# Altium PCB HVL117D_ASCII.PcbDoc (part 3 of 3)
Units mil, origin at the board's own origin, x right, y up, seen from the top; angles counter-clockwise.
Board outline 2004.03 x 2004.03 mil, 6 copper layers (Top Layer, InternalPlane1, MidLayer1, InternalPlane2, MidLayer2, Bottom Layer), stack 60.56 mil thick; 218 components, 157 nets, 658 pads, 273 vias.
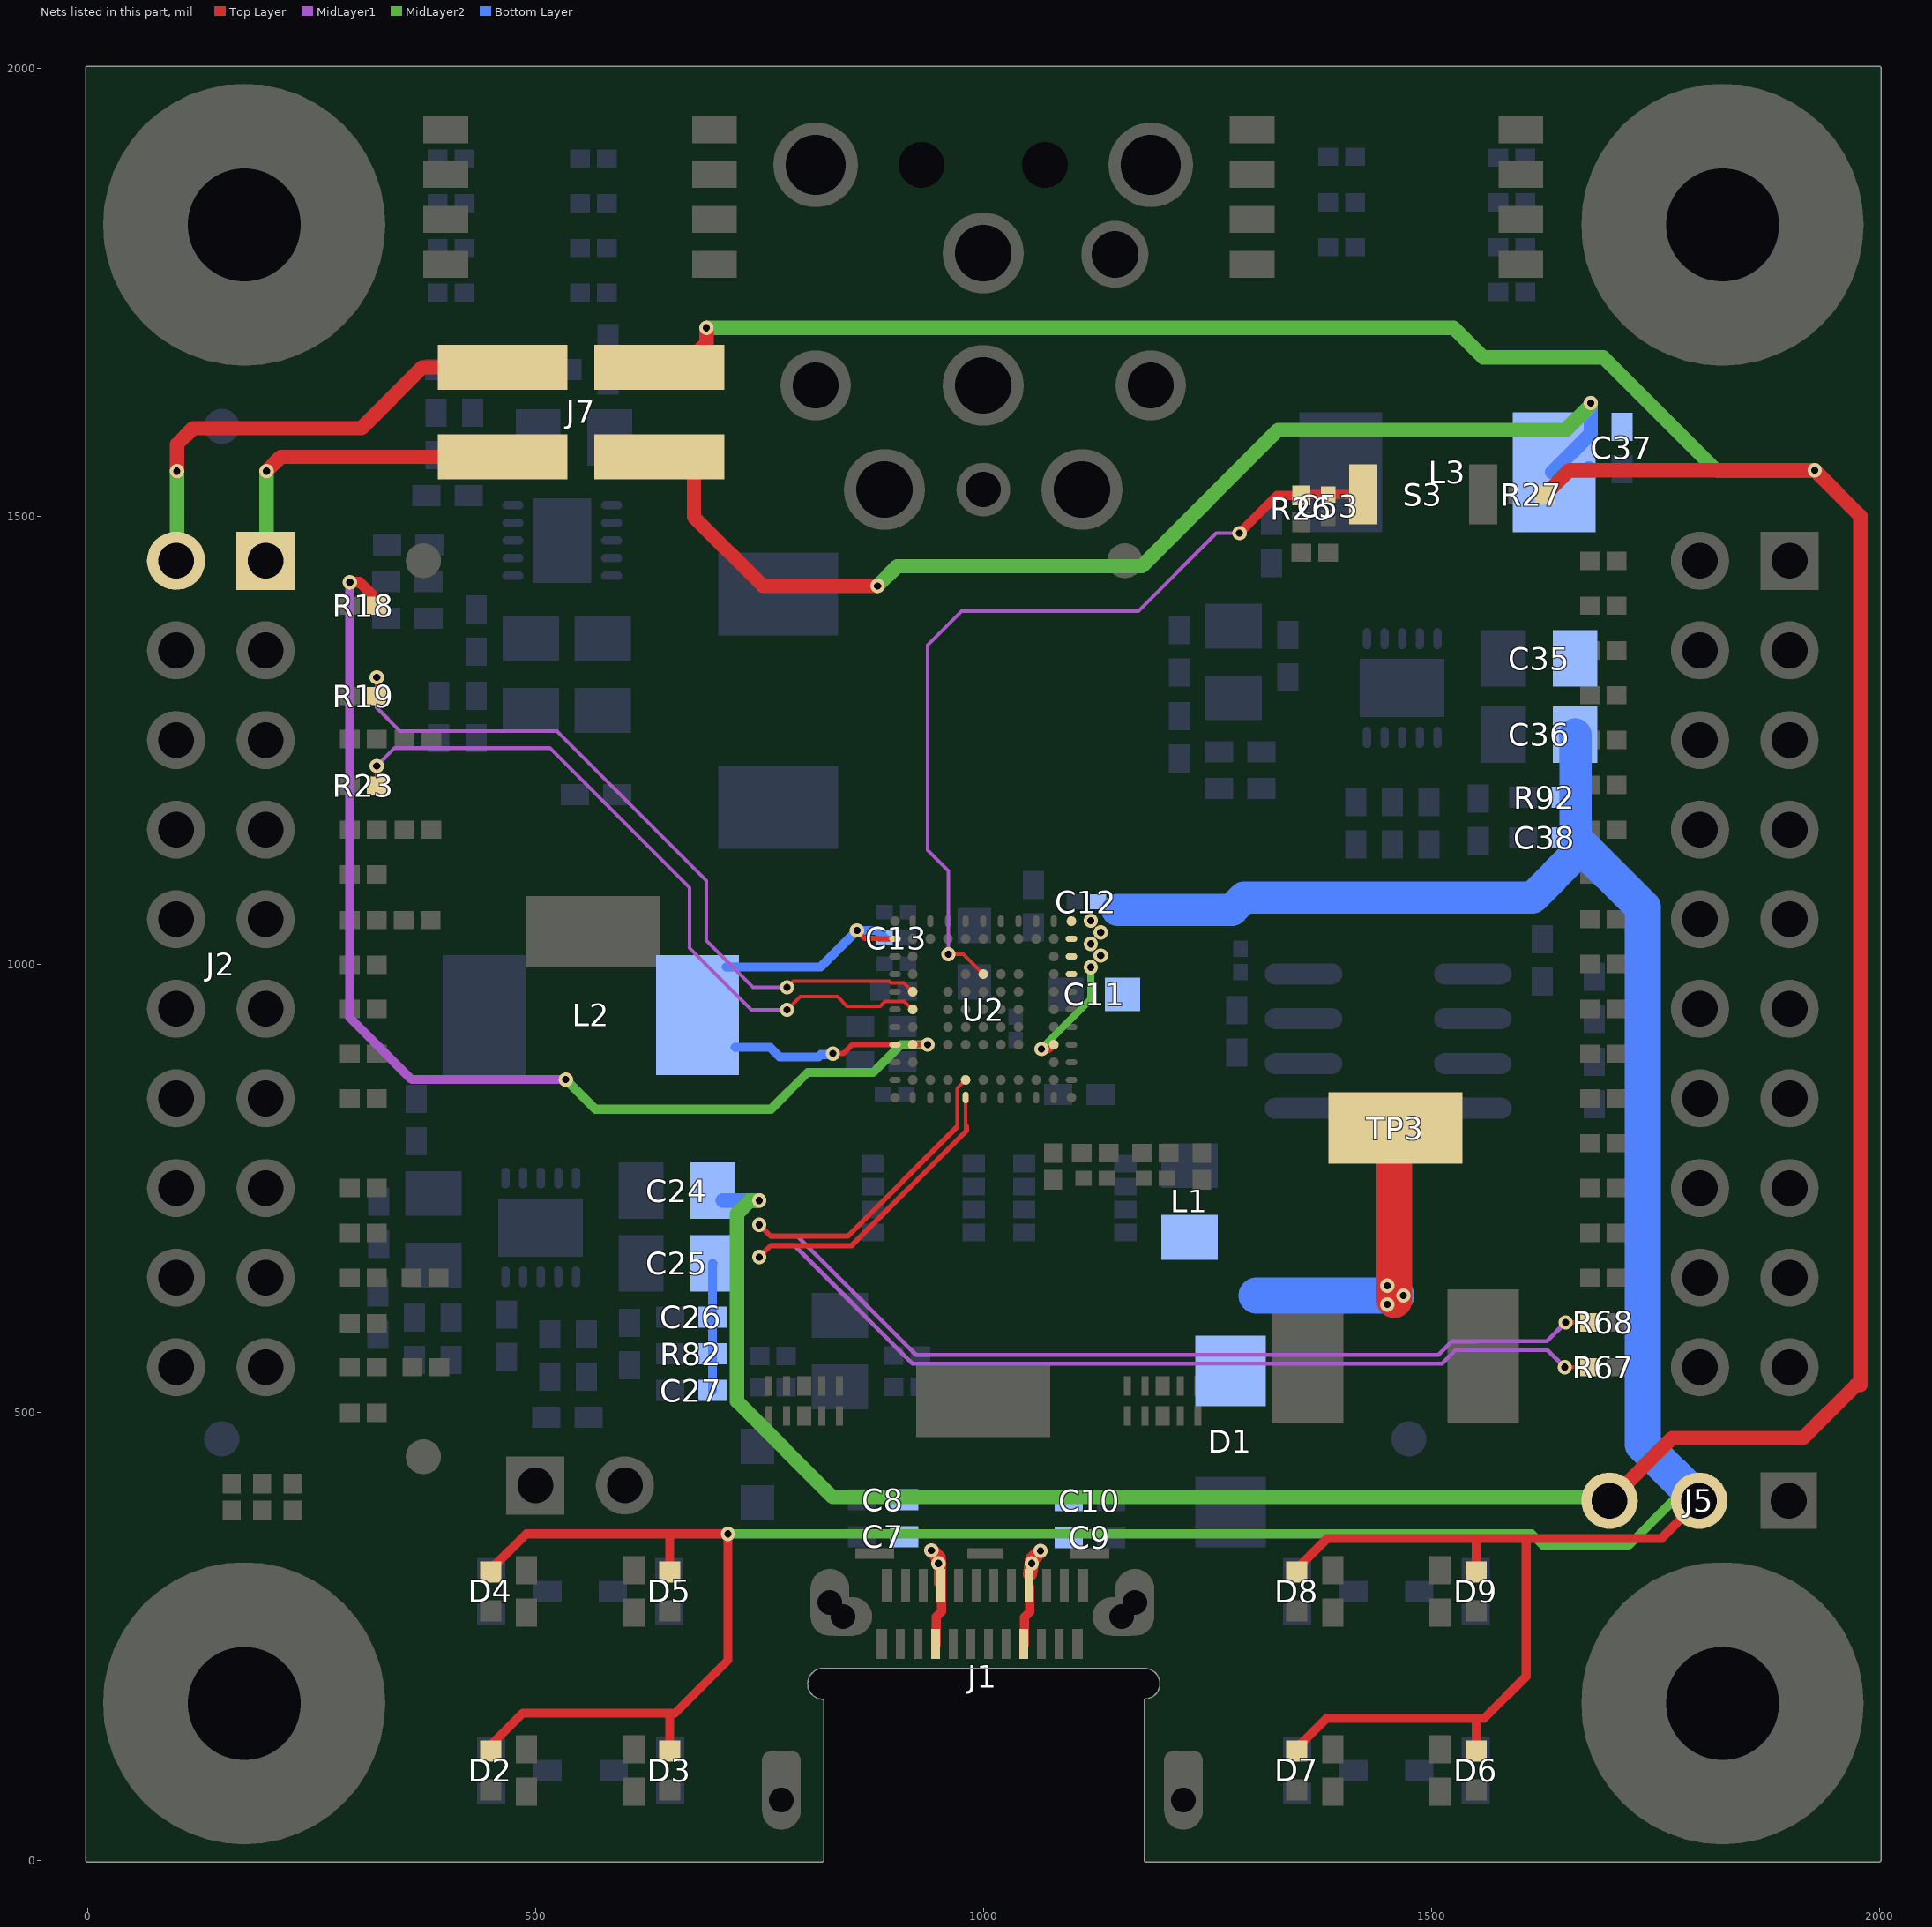
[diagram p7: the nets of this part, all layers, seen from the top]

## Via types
v1: diameter 16, hole 8, Top Layer to Bottom Layer, tented both sides, 166 vias
v2: diameter 16, hole 8.1, Top Layer to Bottom Layer, tented both sides, 54 vias
v3: diameter 20, hole 10, Top Layer to Bottom Layer, tented both sides, 41 vias
v4: diameter 19.68, hole 7.87, Top Layer to Bottom Layer, 12 vias

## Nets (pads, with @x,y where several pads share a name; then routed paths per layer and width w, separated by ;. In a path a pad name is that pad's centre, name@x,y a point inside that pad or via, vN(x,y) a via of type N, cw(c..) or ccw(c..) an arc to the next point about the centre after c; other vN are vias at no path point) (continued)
SYSTEM_3V3: C13.1 C24.1 C25.1 C26.1 C27.1 J5.3 J7.3 L2.2 R27.2 R82.2 U2.B1 U2.H1 | length 4945.8
  Top Layer w6: v1(832,900) 843.63,900 853.63,910 U2.H1@901.57,910 ; v1(859,1037.37) 867.87,1028.5 882.97,1028.5 883.36,1028.11 U2.B1@901.57,1028.11
  Top Layer w16: J7.3@638.5,1666 664,1666 691,1693 v1(691,1710) ; R27.2@1626.96,1524 1653.96,1551 v1(1928,1551) 1979,1500 1979,530 ; J5.3@1699,401 1769,471 1915,471 1974,530
  MidLayer2 w16: v1(691,1710) 1525,1710 1558,1677 1692.05,1677 1818.05,1551 v1(1928,1551) ; v1(750,736) 740,736 725,721 725,512 832,405 1695,405 J5.3@1699,401
  Bottom Layer w6: v1@831,899 v1(832,900) ; v1@861,1033.37 v1@861,1037.37
  Bottom Layer w10: C27.1@697.62,524 C26.1@697.62,606 697.62,665.62 C25.1@698,666 ; L2.2@713.2,996.8 818.43,996.8 v1(859,1037.37) 861,1037.37 881.64,1037.37 C13.1@890.01,1029 ; L2.2@723.1,907.1 762,907.1 772.8,896.3 816.05,896.3 818.75,899 v1@831,899
  Bottom Layer w16: C24.1@709,736 v1(750,736)
SYSTEM_5V: C11.1 C12.1 C35.1 C36.1 C37.1 C38.1 D2.1 D3.1 D4.1 D5.1 D6.1 D7.1 D8.1 D9.1 J5.2 J7.1 L3.2 R92.2 U2.A11 U2.B11 U2.C11 U2.D11 U2.H10 | length 5759.4
  Top Layer w8: v1@1063.8,904.67 1073.41,904.67 U2.H10@1078.74,910
  Top Layer w10: D2.1@450,121.65 450,128 486,164 656,164 715,223 v1(715,364) 490,364 D4.1@455,329 ; D3.1@650,121.65 650,163 ; D5.1@650,321.65 650,361 ; D7.1@1350.5,125.59 1382.91,158 1550,158 ; D8.1@1350.5,325.59 1383.91,359 1606,359 ; D6.1@1550,121.65 1550,158 ; D9.1@1550,321.65 1550,356 ; J5.2@1799,401 1757,359 1606,359 ; 1550,158 1559,158 1606,205 1606,359
  Top Layer w16: 677,1540 677,1499 754,1422 v1(882,1422)
  MidLayer2 w8: v1@1063.8,904.67 1120,960.87 v2(1120,996.37)
  MidLayer2 w10: v1(715,364) 1612,364 1625,351 1720,351 1770,401 J5.2@1799,401
  MidLayer2 w16: v1(882,1422) 904,1444 1177.05,1444 1329.05,1596 1650,1596 v1@1678,1624
  Bottom Layer w16: L3.2@1635.13,1549 1678,1591.87 v1(1678,1626) ; L3.2@1674,1551 L3.2@1676,1553
  Bottom Layer w36: 1150,1060.5 1277.5,1060.5 1291,1074 1613,1074 1661,1122 1661,1255.6 C36.1@1660.6,1256
  Bottom Layer w40: C38.1@1663,1136.4 1736.1,1063.3 1736.1,463.9 J5.2@1799,401
  other v1: 1065,905
  other v2: 1131,1009.37 1120,1022.37 1131,1035.37 1120,1048.37
SYSTEM_RESET: C53.1 R26.2 S3.1 U2.D6 | length 958
  Top Layer w4: v1(961,1011) 977.74,1011 U2.D6@1000,988.74
  Top Layer w10: v1(1286,1481) 1327.96,1522.96 R26.2@1355,1522.96 ; R26.2@1355,1523.96 1382.97,1523.96 1383.01,1524 S3.1@1424.07,1524
  MidLayer1 w4: v1(961,1011) 961,1104 938,1127 938,1356 976,1394 1173,1394 1260,1481 v1(1286,1481)
TIVA_3V3: J2.2 J7.4 | length 529.1
  Top Layer w16: v1(100,1550) 100,1580 118,1598 306,1598 374,1666 J7.4@463.5,1666
  MidLayer2 w16: J2.2@100,1450 v1(100,1550)
TIVA_5V: J2.1 J7.2 | length 370.1
  Top Layer w16: v1(200,1550) 216,1566 J7.2@463.5,1566
  MidLayer2 w16: J2.1@200,1450 v1(200,1550)
UART_RX: R23.2 U2.F2 | length 804.9
  Top Layer w4: R23.2@322.96,1199 R23.2@322.96,1199 v1(323,1221) ; v1(781,949) 795.5,963.5 837.5,963.5 848,953 885,953 890.22,958.22 912,958.22 920.84,949.37 U2.F2@921.26,949.37
  MidLayer1 w4: v1(323,1221) 343,1241 516,1241 672,1085 672,1018 741,949 v1(781,949)
UART_TX: R19.1 U2.E2 | length 829.5
  Top Layer w4: R19.1@322.96,1299 R19.1@322.96,1299 v1(323,1320) ; v1(781,974) 788,981 895,981 897,979 911.31,979 U2.E2@921.26,969.06
  MidLayer1 w4: v1(323,1320) 323,1286 349,1260 523.87,1260 691,1092.87 691,1026 743,974 v1(781,974)
USB2_RP_N: R68.2 U2.K5 | length 1334.1
  Top Layer w4: 971,819 971,861.31 U2.K5@980.32,870.63
  Top Layer w4.8: v1(1650,600) R68.2@1677.04,600
  Top Layer w5.8: v1(750,709) 762.72,696.28 848.78,696.28 970.66,818.16
  MidLayer1 w4.8: v1(750,709) 763.1,695.9 792.96,695.9 925.06,563.8 1508,563.8 1523.2,579 1551,579 1551.06,579.06 1629.06,579.06 v1(1650,600)
USB2_RP_P: R67.2 U2.L5 | length 1327.8
  Top Layer w4: 980.32,819 U2.L5@980.32,850.53
  Top Layer w4.8: v1(1649,550) R67.2@1677.04,550
  Top Layer w5.8: v1(750,673) 762.72,685.72 853.15,685.72 981.21,813.79 981.21,819
  MidLayer1 w4.8: v1(750,673) 763.1,686.1 788.9,686.1 921,554 1512.06,554 1527.26,569.2 1555.06,569.2 1555.12,569.26 1629.74,569.26 v1(1649,550)
VBUS: C7.1 C8.1 C9.1 C10.1 D1.1 J1.A4 J1.A9 J1.B4 J1.B9 L1.2 TP3.1 | length 570.1
  Top Layer w10: J1.B9@947.52,240.35 947.52,271.52 953.42,277.42 J1.A4@953.42,305.31 ; v2(950,331) 950,308.74 J1.A4@953.42,305.31 ; v2@950,337.67 953.42,334.24 J1.A4@953.42,305.31 ; J1.B4@1045.94,240.35 1045.94,270.94 1051.85,276.85 J1.A9@1051.85,305.31
  Top Layer w16: v2(942,345.67) 950,337.67 v2(950,331) ; J1.A9@1052,319 v2(1054,331) 1054,335 v2(1064,345)
  Top Layer w40: 1459,625 TP3.1@1459,793.71
  Bottom Layer w6: 1303,641 1304,640
  Bottom Layer w40: 1305,630 v1@1461,630
  other v1: 1451,620 1469,630 1451,641
VOUT_3V3: R18.1 U2.H2 | length 1267.8
  Top Layer w6: U2.H2@921.26,910 v1(938,910) 940.63,910 v1@941,910.37
  Top Layer w10: R18.1@322.96,1400 R18.1@322.96,1407.04
  Top Layer w12: v1(293,1426) 304,1426 R18.1@322.96,1407.04
  MidLayer1 w10: v1(293,1426) 293,940 362,871 v1(534,871)
  MidLayer2 w10: v1(534,871) 567,838 763,838 804,879 877,879 908,910 v1(938,910)
pads on no net: FID1.1 FID2.1 FID3.1 FID4.1 FID5.1 FID6.1 H1.1 H2.1 H3.1 H4.1 J1.A2 J1.A3 J1.A10 J1.A11 J1.B2 J1.B3 J1.B10 J1.B11 J4.10 J4.11 U2.L11

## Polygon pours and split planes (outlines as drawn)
VBUS on Bottom Layer "Mid Layer2 GND Pour" (solid, pour order 11): 890,434 890,450 964,524 1031,591 1150,591 1165,591 1198,624 1198,486 1197,486 1145,434 1120,434
GND on Bottom Layer "Mid Layer2 GND Pour" (solid, remove dead copper, pour order 18): 11,1984 1983,1984 1983,18 1203,18 1202,19 1201,20 1201,147 1201,148 1226,173 1226,214 1226,215 1199,242 802,242 772,212 771,211 771,171 772,171 799,144 799,17 13,17
GND on Top Layer "Mid Layer2 GND Pour" (solid, remove dead copper, pour order 6): 901,1048.37 901.57,1047.8 1098.43,1047.8 1098.43,850.94 901.57,850.94 901.57,1047.8
GND on MidLayer2 "Mid Layer2 GND Pour" (solid, remove dead copper, pour order 20): 16,1983 17,1984 1983,1984 1983,17 1984,16 1983,17 1199,17 1199,148 1223,172 1223,217 1205,235 1205,239 1205,235 1200,240 801,240 799,240 773,214 774,213 774,169 800,143 801,142 801,16 14,16
GND on InternalPlane1 (split plane): 1982.08,18.08 1199.64,17.92 1199.5,163.44 1203.49,166.11 1205.99,168.16 1206.54,168.61 1206.98,169.15 1209.04,171.65 1213.39,178.16 1215.24,181.64 1216.39,185.41 1217.92,193.09 1218.24,196.36 1218.3,197.01 1218.24,197.65 1217.92,200.93 1216.39,208.61 1215.24,212.38 1213.39,215.85 1209.04,222.37 1206.98,224.86 1206.54,225.41 1205.99,225.86 1203.49,227.91 1196.98,232.26 1193.51,234.12 1189.74,235.26 1182.05,236.79 1178.13,237.18 1174.22,236.79 823.78,236.79 819.87,237.18 819.51,237.14 815.95,236.79 808.26,235.26 804.49,234.12 801.02,232.26 794.51,227.91 792.01,225.86 791.46,225.41 791.02,224.86 788.96,222.37 784.61,215.85 782.76,212.38 781.61,208.61 780.08,200.93 779.7,197.01 780.08,193.09 781.61,185.41 782.76,181.64 784.61,178.16 788.96,171.65 791.02,169.15 791.46,168.61 792.01,168.16 794.51,166.11 799.77,162.59 799.77,18.08 18.08,17.92 17.92,1981.92 1981.92,1982.08
GND on InternalPlane2 (split plane): 2001.5,2001.5 2002.1,2000.05 2002.01,2000.05 2001.98,2000.04 2001.96,2000 2002.13,0.01 2001.5,-1.5 2000.05,-2.1 2000.05,-2.02 2000.04,-1.98 2000,-1.96 1181.59,-2.13 1180.07,-1.5 1179.47,-0.05 1179.56,-0.05 1179.6,-0.04 1179.61,0 1179.45,176.41 1179.75,177.14 1179.75,177.15 1179.75,177.16 1179.75,177.18 1179.74,177.18 1179.74,177.2 1185.83,178.41 1185.83,178.42 1185.84,178.42 1192.36,182.77 1192.36,182.78 1192.37,182.79 1196.72,189.3 1196.72,189.31 1196.73,189.32 1198.26,197 1198.26,197.01 1198.26,197.02 1196.73,204.7 1196.72,204.71 1196.72,204.72 1192.37,211.23 1192.36,211.24 1192.36,211.25 1185.84,215.6 1185.83,215.6 1178.14,217.13 1178.13,217.13 1178.12,217.13 1178.1,217.12 1178.09,217.1 1178.08,217.09 1178.08,217.08 1178.08,216.75 819.92,216.75 819.92,217.08 819.92,217.09 819.91,217.1 819.9,217.12 819.88,217.13 819.87,217.13 819.86,217.13 812.17,215.6 812.16,215.6 805.64,211.25 805.64,211.24 805.63,211.23 801.28,204.72 801.28,204.71 801.27,204.7 799.74,197.02 799.74,197.01 799.74,197 801.27,189.32 801.28,189.31 801.28,189.3 805.63,182.79 805.64,182.78 805.64,182.77 812.16,178.42 812.17,178.42 812.17,178.41 819.81,176.89 819.81,10 819.83,9.96 819.87,9.95 822.12,9.95 822.13,0.01 821.5,-1.5 820.05,-2.1 820.05,-2.02 820.04,-1.98 820,-1.96 0.01,-2.13 -1.5,-1.5 -2.1,-0.05 -2.01,-0.05 -1.98,-0.04 -1.96,0 -2.13,1999.99 -1.5,2001.5 -0.05,2002.1 -0.05,2002.01 -0.04,2001.98 0,2001.96 1999.99,2002.13

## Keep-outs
Keep-Out Layer:
  lines w10: -5,3450 cw(c0,3450) 0,3455 ; -5,3450 cw(c0,3450) 0,3455 ; -5,3450 cw(c0,3450) 0,3455 ; -5,3450 cw(c0,3450) 0,3455 ; -5,3450 cw(c0,3450) 0,3455 ; -5,3450 cw(c0,3450) 0,3455 ; 4950,3455 cw(c4950,3450) 4955,3450 ; 4950,3455 cw(c4950,3450) 4955,3450 ; 4950,3455 cw(c4950,3450) 4955,3450 ; 4950,3455 cw(c4950,3450) 4955,3450 ; 4950,3455 cw(c4950,3450) 4955,3450 ; 4950,3455 cw(c4950,3450) 4955,3450
  text ".Layer_Name" at 577,-858.49 h60

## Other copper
Top Layer:
  rectangle net GND: 761,240 891,356
  rectangle net GND: 1106,239 1234,356
  rectangle net GND: 787,269 900,356
  rectangle net HV_SOURCE: 996.01,1059.37 1042,1105.59
  region net NetC6_1: 1112.6,913.17 1112.6,867.37 1152,867.37 1152,913.17
  rectangle net C_SBU_P: 1027.24,319 1034,331
  rectangle net DEBUG_CTL1: 951.6,964.2 961,969.06
  rectangle net GND: 490,1048 640,1096
  rectangle net SYSTEM_3V3: 691,1684 699,1693
  text ".Layer_Name" at 577,-858.49 h60
Bottom Layer:
  rectangle net NetC6_1: 1109,842 1166,914
  rectangle net GND: 497,1337 598,1477
  rectangle net GND: 422,1380 518,1415
  rectangle net GND: 498,1507 549,1632
  rectangle net GND: 377,1591 524,1632
  rectangle net VBUS: 890,395 1120,434
  rectangle net VBUS: 1198,486 1262,719
  rectangle net NetQ1_5: 910,683 1124,795
  rectangle net NetC1_1: 683,443 767,503
  rectangle net NetC1_1: 662,442 758.5,451.5
  rectangle net GND: 452.3,671.1 548,738.5
  rectangle net GND: 548,671.1 655.3,739.4
  rectangle net GND: 499.7,739.4 655.3,778.9
  rectangle net GND: 589,634.8 656,773.8
  rectangle net GND: 500,722.6 583.1,747.2
  rectangle net SYSTEM_3V3: 671.7,633.4 729.4,1009.6
  rectangle net GND: 1246,1271 1617,1335
  rectangle net GND: 1463,1314 1585,1375
  rectangle net GND: 1534.53,1224 1619,1374.93
  rectangle net "EXTERNAL POWER": 1207.3,1351.5 1433.3,1380.4
  rectangle net GND: 1245.5,1297.6 1372.1,1340.3
  rectangle net SYSTEM_5V: 1632.3,1222.9 1687.3,1616
  rectangle net "EXTERNAL POWER": 574,1507 871,1581
  rectangle net VBUS: 1209,486 1316,531
  rectangle net SYSTEM_5V: 1668,1584 1726,1616
  rectangle net SYSTEM_5V: 1632.3,1085 1687,1222.9
  text ".Layer_Name" at 577,-858.49 h60
InternalPlane1 (plane layer: these items are gaps in the copper):
  lines w40: 819.87,216.69 819.87,217.08 812.19,215.55 805.67,211.2 801.32,204.69 799.8,197.01 801.32,189.33 805.67,182.82 812.19,178.46 819.87,176.94 819.87,10 822.17,10 822.18,0 821.54,-1.54 820,-2.02 0,-2.18 -1.54,-1.54 -2.01,0 -2.18,2000 -1.54,2001.54 0,2002.01 2000,2002.18 2001.54,2001.54 2002.01,2000 2002.18,0 2001.54,-1.54 2000,-2.02 1181.57,-2.18 1180.03,-1.54 1179.56,0 1179.39,176.43 1179.7,177.16 1179.66,177.24 1185.81,178.46 1192.33,182.82 1196.68,189.33 1198.2,197.01 1196.68,204.69 1192.33,211.2 1185.81,215.55 1178.13,217.08 1178.13,216.69 819.87,216.69 ; 819.87,216.69 819.87,216.69
InternalPlane2 (plane layer: these items are gaps in the copper):
  lines w0.1: 819.87,216.69 819.87,217.08 812.19,215.55 805.67,211.2 801.32,204.69 799.8,197.01 801.32,189.33 805.67,182.82 812.19,178.46 819.87,176.94 819.87,10 822.17,10 822.18,0 821.54,-1.54 820,-2.02 0,-2.18 -1.54,-1.54 -2.01,0 -2.18,2000 -1.54,2001.54 0,2002.01 2000,2002.18 2001.54,2001.54 2002.01,2000 2002.18,0 2001.54,-1.54 2000,-2.02 1181.57,-2.18 1180.03,-1.54 1179.56,0 1179.39,176.43 1179.7,177.16 1179.66,177.24 1185.81,178.46 1192.33,182.82 1196.68,189.33 1198.2,197.01 1196.68,204.69 1192.33,211.2 1185.81,215.55 1178.13,217.08 1178.13,216.69 819.87,216.69 ; 819.87,216.69 819.87,216.69

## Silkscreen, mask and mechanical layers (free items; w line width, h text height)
Top Overlay:
  drawing of 1037 lines, arcs and shapes, not listed
  text "+" at 1140,1951 h50
  text "GND" at 949,1950 h50
  text "TPS65982EVM" at 50,1619 h50
  text "HVL117" at 137,1591 h30
  text "SVN: REV D" at 137.2,1565 h30
  text "19V-20V" at 767,1519 h50 r90
  text "RESET" at 1421,1396 h50
  text "TPS65982 BoosterPack" at 777,1214 h75
  text "USB Type-C & PD" at 777,1152 h65
  text "GND" at 586,941 h40
  text "VBUS" at 1411,885 h40
  text "CC2" at 1329,661 h40
  text "CC1" at 1527,660 h40
  text "PP_EXT" at 477,516 h40
  text "ENABLE" at 478,478 h40
  text "GND" at 961,416 h40
  text "5V" at 1343,357 h60
  text "HV" at 1492,357 h60
  text "A" at 383,215 h60
  text "B" at 689,215 h60
  text "PVDR" at 1306,162 h60
  text "CONS" at 1462,162 h60
  text "CC1" at 425,161 h60
  text "CC2" at 585,160 h60
  text ".Layer_Name" at 577,-858.49 h60
Bottom Overlay:
  rectangle: 1442,594 1742,694
  text ".PRJ_Number" at 1736,719 h50
  text ".Layer_Name" at 577,-858.49 h60
Top Paste:
  text ".Layer_Name" at 577,-858.49 h60
Bottom Paste:
  text ".Layer_Name" at 577,-858.49 h60
Top Solder:
  text ".Layer_Name" at 577,-858.49 h60
  text ".Layer_Name" at 577,-858.49 h60
Bottom Solder:
  text ".Layer_Name" at 577,-858.49 h60
Drill Guide:
  text ".Layer_Name" at 577,-858.49 h60
M1 Board Outline:
  lines w4: 818.96,177.51 cw(c821.31,196.68) 821.31,216 1180,216 cw(c1180,196.89) 1181.59,177.86 ; 820,177.51 820,0 0,0 0,2000 2000,2000 2000,0 1181.57,0 1181.57,176.43
  text ".Layer_Name" at 577,-858.49 h60
M2 Board Dimensions:
  rectangle: 125,-410.5 500,-285.5
  rectangle: 0,-285.5 125,-160.5
  lines w7: 0,-285.5 1000,-285.5 ; 125,-410.5 125,-160.5 ; 250,-410.5 250,-160.5 ; 500,-410.5 500,-160.5 ; 750,-410.5 750,-160.5 ; 0,-410.5 0,-160.5 1000,-160.5 1000,-410.5 0,-410.5
  text ".Layer_Name" at 577,-858.49 h60
M3 3D STEP Top:
  text ".Layer_Name" at 577,-858.49 h60
M4 3D STEP Bottom:
  text ".Layer_Name" at 577,-858.49 h60
M5 Assembly Top:
  lines w10: -292,-930.17 6308,-930.17 ; -292,-726.83 6310,-726.83 ; -292,-523.5 -292,-1133.5 3713,-1133.5 6310,-1133.5 6310,-523.5 -291.5,-523.5 -291.5,-1133.5 1284,-1133.5 ; 2173,-1133.5 2173,-523.5 ; 3440,-726.83 3440,-523.5 ; 4280,-726.83 4280,-523.5 ; 4902,-1140 4902,-937.17
  text "COMPONENTS MARKED 'DNP' SHOULD NOT BE POPULATED." at 1153.5,-318.5 h60
  text "ASSEMBLY VARIANT:" at 1153,-434 h60
  text ".VariantName" at 2189,-434 h60
  text "PCB VIEWED FROM TOP SIDE" at -228.5,-655.67 h60
  text "BOARD #:" at 2248,-655.67 h60
  text ".PRJ_Number" at 2793.5,-655.67 h60
  text "REV:" at 3638,-655.67 h60
  text ".PCB_Rev" at 3929.5,-655.67 h60
  text "SVN REV:" at 4476,-655.67 h60
  text ".VersionControl_RevNumber" at 4982,-655.67 h60
  text "IGNORE ->" at -228.5,-858.49 h60
  text "PLOT NAME =" at -228.5,-1064.34 h60
  text ".plot_File_Name" at 577,-1064.34 h60
  text "GENERATED    :" at 2250,-1064.34 h60
  text ".Print_Date" at 3119.5,-1064.34 h60
  text ".Print_Time" at 3848.5,-1064.34 h60
  text "TEXAS INSTRUMENTS" at 5113,-1064.34 h60
M6 Assembly Bottom:
  lines w10: -292.5,-727.33 6309.5,-727.33 ; -290.5,-930.67 6309.5,-930.67 ; 1115.5,-1140.5 1115.5,-937.67 ; 1737.5,-727.33 1737.5,-524 ; 2577.5,-727.33 2577.5,-524 ; 3844.5,-1134 3844.5,-524 ; 4733.5,-1134 6309,-1134 6309,-524 -292.5,-524 -292.5,-1134 2304.5,-1134 6309.5,-1134 6309.5,-524
  text "COMPONENTS MARKED 'DNP' SHOULD NOT BE POPULATED." at 6102,-318 h60
  text ".VariantName" at 5058,-434 h60
  text "ASSEMBLY VARIANT:" at 6097,-434 h60
  text ".VersionControl_RevNumber" at 1035.5,-656.17 h60
  text "SVN REV:" at 1541.5,-656.17 h60
  text ".PCB_Rev" at 2088,-656.17 h60
  text "REV:" at 2379.5,-656.17 h60
  text ".PRJ_Number" at 3224,-656.17 h60
  text "BOARD #:" at 3769.5,-656.17 h60
  text "PCB VIEWED FROM BOTTOM SIDE" at 6246,-656.17 h60
  text "IGNORE ->" at 2547.85,-858.49 h60
  text "TEXAS INSTRUMENTS" at 904.5,-1064.84 h60
  text ".Print_Time" at 2169,-1064.84 h60
  text ".Print_Date" at 2898,-1064.84 h60
  text "GENERATED    :" at 3767.5,-1064.84 h60
  text ".plot_File_Name" at 5440.5,-1064.84 h60
  text "PLOT NAME =" at 6246,-1064.84 h60
M9 Title Sheet:
  lines w10: -491.5,1041.5 -291.5,1041.5 ; -491.5,3416.5 -291.5,3416.5 ; -491.5,5791.5 -291.5,5791.5 ; 2008.5,-1333.5 2008.5,-1133.5 ; 2008.5,7966.5 2008.5,8166.5 ; 4508.5,-1333.5 4508.5,-1133.5 ; 4508.5,7966.5 4508.5,8166.5 ; 6321,-1133.5 6321,-523.5 11303.5,-523.5 ; 7008.5,-1333.5 7008.5,-1133.5 ; 7008.5,7966.5 7008.5,8166.5 ; 9508.5,-1333.5 9508.5,-1133.5 ; 9508.5,7966.5 9508.5,8166.5 ; 11303.5,-1133.5 11303.5,-523.5 ; 11303.5,-823.5 14303.5,-823.5 ; 11303.5,-223.5 14303.5,-223.5 ; 11304.5,370.5 14304.5,370.5 ; 12008.5,-1333.5 12008.5,-1133.5 ; 12008.5,7966.5 12008.5,8166.5 ; 12808.5,-1123.5 12808.5,-523.5 ; 14303.5,-523.5 11303.5,-523.5 ; 14303.5,76.5 11303.5,76.5 ; 14308.5,66.5 14308.5,-1133.5 ; 14308.5,871 11304.5,871 11303.5,871 11303.5,370.5 11303.5,76.5 ; 14308.5,1041.5 14508.5,1041.5 ; 14308.5,3416.5 14508.5,3416.5 ; 14308.5,5791.5 14508.5,5791.5 ; 11303.5,-523.5 11303.5,76.5 ; 14308.5,-1133.5 -291.5,-1133.5 -291.5,7966.5 14308.5,7966.5 14308.5,-1133.5 ; -491.5,-1333.5 14508.5,-1333.5 14508.5,8166.5 -491.5,8166.5 -491.5,-1333.5
  text "1" at 739.84,8036.5 h70
  text "2" at 3235.5,8036.5 h70
  text "3" at 5724.84,8036.5 h70
  text "4" at 8231.51,8036.5 h70
  text "5" at 10730.5,8036.5 h70
  text "6" at 13235.5,8036.5 h70
  text "A" at -416.5,6893.5 h70
  text "A" at 14383.5,6893.5 h70
  text "B" at -416.5,4513.5 h70
  text "B" at 14383.5,4513.5 h70
  text "C" at -416.5,2138.5 h70
  text "C" at 14383.5,2138.5 h70
  text "PROJECT TITLE:" at 11343.5,277.5 h45
  text ".PRJ_Title" at 11393.5,144.17 h70
  text "DESIGNED FOR:" at 11343.5,-23.5 h45
  text ".PRJ_Customer" at 11393.5,-163.5 h70
  text "D" at -416.5,-231.5 h70
  text "D" at 14383.5,-231.5 h70
  text "FILE NAME:" at 11343.5,-323.5 h45
  text ".PCB_File_Name_No_Path" at 11393.5,-443.5 h70
  text "Texas Instruments (TI) and/or its licensors do not warrant the accuracy or completeness of this specification" at 6374,-605.34 h45
  text "ENGINEER:" at 11343.5,-613.5 h45
  text "LAYOUT BY:" at 12848.5,-613.5 h45
  text "or any information contained therein. TI and/or its licensors do not warrant that this design will meet" at 6329.01,-718 h45
  text ".PRJ_Engineer" at 11393.5,-768.49 h70
  text ".PCB_Layout" at 12899,-768.49 h70
  text "the specifications, will be suitable for your application or fit for any particular purpose, or will operate in" at 6329.01,-830.67 h45
  text ".Layer_Name" at 577,-858.49 h60
  text "ALTIUM DESIGNER VERSION:" at 12848.5,-923.5 h45
  text "an implementation. TI and/or its licensors do not warrant that the design is production worthy. You should" at 6329.01,-943.33 h45
  text "completely validate and test your design implementation to confirm the system functionality for your application." at 6374,-1056 h45
  text ".print_Scale" at 11393.5,-1056.83 h70
  text ".Application_BuildNumber" at 12899,-1056.83 h70
  text "1" at 739.84,-1263.5 h70
  text "2" at 3235.5,-1263.5 h70
  text "3" at 5724.84,-1263.5 h70
  text "4" at 8231.51,-1263.5 h70
  text "5" at 10730.5,-1263.5 h70
  text "6" at 13235.5,-1263.5 h70
M10 Fab Notes:
  drawing of 185 lines, arcs and shapes, not listed
  text "DESIGN INFORMATION" at 12381.02,5910 h60
  text "MIN. TRACK WIDTH:" at 11736.46,5730 h60
  text "4" at 12832.7,5730 h60
  text "MIL" at 12987.46,5730 h60
  text "MIN. CLEARANCE:" at 11736.46,5598 h60
  text "0.2" at 12772.7,5598 h60
  text "mm" at 12987.46,5598 h60
  text "MIN. VIA PAD SIZE:" at 11736.46,5466 h60
  text "16" at 12802.71,5466 h60
  text "MIL" at 12987.46,5466 h60
  text "0.05mm (2MIL)" at 12431.46,5324.29 h60
  text "MINIMUM ANNULAR RING" at 11407.23,5320 h60
  text "EXTERNAL" at 13139.46,5320 h60
  text "PER" at 11607.23,5202 h60
  text "IPC-D-275 CLASS 2 LEVEL C" at 11827.23,5202 h60
  text "MIL, HOLES" at 13315.46,5089.71 h60
  text "+/-" at 12923,5089 h60
  text "+/-" at 13777,5089 h60
  text "REGISTRATION TOLERANCES:" at 11407.23,5084 h60
  text "METAL" at 12607,5084 h60
  text "5" at 13183.2,5084 h60
  text "3" at 14016.2,5084 h60
  text "MIL" at 14132.46,5084 h60
  text "MATERIAL:" at 11332.46,4874.54 h60
  text "FR-4 High Tg" at 12318.9,4734.21 h60
  text "FR-408" at 11753.46,4725.64 h60
  text "X" at 12165.46,4725.64 h60
  text "OTHER" at 13241.46,4725.64 h60
  text "62 MIL (1.6mm) +/-10%" at 12073.56,4562.92 h60
  text "THICKNESS:" at 11407.23,4558.64 h60
  text "X" at 11945.4,4558.64 h60
  text "OTHER" at 13358.46,4558.64 h60
  text "TOLERANCE:" at 11407.23,4400.64 h60
  text "X" at 12246.53,4400.64 h60
  text "ANSI IPC-6012 TYPE 3 CLASS 2" at 12433.48,4400.64 h60
  text "IMPEDANCE CONTROL:" at 5720,4310 h120
  text "OTHER +/-" at 12433.46,4244.64 h60
  text "BOW & TWIST:" at 11407.23,4087.64 h60
  text "X" at 12246.53,4087.64 h60
  text "ANSI IPC-6012 TYPE 3 CLASS 2" at 12433.48,4087.64 h60
  text "Layer 1:" at 5726,4069 h120
  text "OTHER +/-" at 12433.46,3929.13 h60
  text "100 OHM differential : 5.0mil trace- 5.5mil spacing" at 5720,3822 h120
  text "DRILLING:" at 11332.46,3790.64 h60
  text "REFERENCE:" at 11407.23,3673.64 h60
  text "X" at 12055.46,3673.64 h60
  text "AS SHOWN" at 12242.46,3673.64 h60
  text "X" at 12956.46,3673.64 h60
  text "NC_DRILL FILES" at 13093.46,3673.64 h60
  text "90 OHM differential : 5.8mil trace- 4.75mil spacing" at 5720,3575 h120
  text "PTH MIN COPPER THICKNESS:" at 11407.23,3515.64 h60
  text "X" at 12757.46,3515.64 h60
  text "1MIL" at 12894.46,3515.64 h60
  text "OTHER" at 13391.46,3515.64 h60
  text "BOARD FINISH:" at 11332.46,3356.64 h60
  text "50 OHM Single-ended : 9.8mil trace" at 5714,3334 h120
  text "SILKSCREEN:" at 11487.68,3238.64 h60
  text "X" at 12436.46,3238.64 h60
  text "TOP" at 12562.46,3238.64 h60
  text "X" at 12946.46,3238.64 h60
  text "BOTTOM" at 13073.46,3238.64 h60
  text "Layer 3:" at 5703,3127 h120
  text "SILKSCREEN COLOR:" at 11487.68,3071.64 h60
  text "X" at 12435.42,3071.64 h60
  text "WHITE" at 12562.46,3071.64 h60
  text "OTHER" at 13073.46,3071.64 h60
  text "SOLDER RESIST COLOR:" at 11487.68,2901.64 h60
  text "100 OHM differential : 4.4mil trace- 6.5mil spacing" at 5686,2869 h120
  text "RED" at 13782,2744 h100
  text "GREEN" at 12182.46,2742.44 h60
  text "BLUE" at 12773.46,2742.44 h60
  text "OTHER" at 13311.46,2742.44 h60
  text "X" at 13166,2740 h60
  text "90 OHM differential : 4.8mil trace- 5.0mil spacing" at 5686,2622 h120
  text "IMMERSION GOLD (ENIG)" at 12393.46,2553.92 h60
  text "ENEPIG" at 13731,2550.64 h60
  text "SURFACE FINISH:" at 11332.46,2549.64 h60
  text "X" at 12206.51,2549.64 h60
  text "IMM. TIN/SILVER OR EQUIV" at 11662,2392.64 h60
  text "OTHER" at 13093.46,2392.64 h60
  text "50 OHM Single-ended : 9.1mil trace" at 5680,2381 h120
  text "ARRAY/PANEL:" at 11332.46,2213.64 h60
  text "CUT AND TRIM PER MECH LAYER 1" at 12393.46,2209.35 h60
  text "N.C. ROUTE" at 12393.46,2057.64 h60
  text "X" at 13072.46,2057.64 h60
  text "V. SCORE" at 13259.46,2057.64 h60
  text "CERTIFICATION:" at 11332.46,1920.64 h60
  text "MATERIALS AND WORKMANSHIP FOR ALL PCBS" at 12057.46,1920.64 h60
  text "TO MEET OR EXCEED THE REQUIREMENTS OF:" at 12057.46,1822.64 h60
  text "VIA FILL FOR ALL 8.1 MIL VIAS USING NON CONDUCTIVE EPOXY." at 5644,1787 h120
  text "X" at 11683.96,1686.13 h60
  text "ANSI IPC-A-600F CLASS ->" at 11822.96,1686.13 h60
  text "X" at 13462.02,1686.13 h60
  text "2" at 13580.96,1686.14 h60
  text "1" at 13265.96,1684.64 h60
  text "3" at 13934.96,1684.64 h60
  text "X" at 11686.02,1526.64 h60
  text "UL 94V-0" at 11822.96,1526.64 h60
  text "X" at 12498.02,1526.64 h60
  text "RoHS" at 12634.96,1526.64 h60
  text "OTHER" at 13279.36,1526.64 h60
  text "PER ORDER" at 13676.42,1526.64 h60
  text "***ATTENTION***" at 5651,1436 h120
  text "ADDITIONAL REQUIREMENTS:" at 11332.46,1385.64 h60
  text "MICROSECTION:" at 11407.23,1270.64 h60
  text "YES" at 12312.96,1270.64 h60
  text "J2 and J3 headers are to be installed on bottom side of board" at 5658,1194 h120
  text "REQUIRED" at 13174.46,1114.49 h60
  text "BARE BOARD ELEC. TEST:" at 11407.23,1111.64 h60
  text "NONE" at 12712.96,1111.64 h60
  text "X" at 13047.46,1111.64 h60
  text "PER ORDER" at 13766.46,1111.64 h60
  text "MANUFACTURER'S UL:" at 11407.23,954.64 h60
  text "RAIL" at 12572.96,950.35 h60
  text "METAL" at 13064.77,950.35 h60
  text "X" at 13440,950 h60
  text "SILK" at 13576.46,950.35 h60
  text ".Layer_Name" at 577,-858.49 h60
M11 Gerber Information:
  lines w10: -292,-930.17 6308,-930.17 ; -292,-726.83 6310,-726.83 ; -292,-523.5 -292,-1133.5 3713,-1133.5 6310,-1133.5 6310,-523.5 -291.5,-523.5 -291.5,-1133.5 1284,-1133.5 ; 2173,-1133.5 2173,-523.5 ; 3440,-726.83 3440,-523.5 ; 4280,-726.83 4280,-523.5 ; 4902,-1140 4902,-937.17
  text "ALL ARTWORK VIEWED FROM TOP SIDE" at -228.5,-655.67 h60
  text "BOARD #:" at 2248,-655.67 h60
  text ".PRJ_Number" at 2793.5,-655.67 h60
  text "REV:" at 3638,-655.67 h60
  text ".PCB_Rev" at 3929.5,-655.67 h60
  text "SVN REV:" at 4476,-655.67 h60
  text ".VersionControl_RevNumber" at 4982,-655.67 h60
  text "LAYER NAME =" at -228.5,-858.49 h60
  text "PLOT NAME =" at -228.5,-1064.34 h60
  text ".plot_File_Name" at 577,-1064.34 h60
  text "GENERATED    :" at 2250,-1064.34 h60
  text ".Print_Date" at 3119.5,-1064.34 h60
  text ".Print_Time" at 3848.5,-1064.34 h60
  text "TEXAS INSTRUMENTS" at 5113,-1064.34 h60
M12 Stackup:
  drawing of 399 lines, arcs and shapes, not listed
  text "Layer" at 9812,7859 h60
  text "Name" at 10221.91,7859 h60
  text "Material" at 11151.66,7859 h60
  text "Thickness" at 12011.42,7859 h60
  text "Constant" at 12661.26,7859 h60
  text "Board Layer Stack" at 13231.12,7859 h60
  text "1" at 9812,7739 h60
  text "Top Overlay" at 10221.91,7739 h60
  text "2" at 9812,7619 h60
  text "Top Solder" at 10221.91,7619 h60
  text "Solder Resist" at 11151.66,7619 h60
  text "0.80mil" at 12011.42,7619 h60
  text "3.3" at 12661.26,7619 h60
  text "3" at 9812,7499 h60
  text "Top Layer" at 10221.91,7499 h60
  text "Copper" at 11151.66,7499 h60
  text "1.40mil" at 12011.42,7499 h60
  text "4" at 9812,7379 h60
  text "Dielectric1" at 10221.91,7379 h60
  text "FR-4" at 11151.66,7379 h60
  text "5.91mil" at 12011.42,7379 h60
  text "4.1" at 12661.26,7379 h60
  text "5" at 9812,7259 h60
  text "InternalPlane1" at 10221.91,7259 h60
  text "Copper" at 11151.66,7259 h60
  text "1.40mil" at 12011.42,7259 h60
  text "6" at 9812,7139 h60
  text "Dielectric4" at 10221.91,7139 h60
  text "FR-4" at 11151.66,7139 h60
  text "7.87mil" at 12011.42,7139 h60
  text "4.1" at 12661.26,7139 h60
  text "7" at 9812,7019 h60
  text "MidLayer1" at 10221.91,7019 h60
  text "Copper" at 11151.66,7019 h60
  text "1.40mil" at 12011.42,7019 h60
  text "8" at 9812,6899 h60
  text "Dielectric2" at 10221.91,6899 h60
  text "FR-4" at 11151.66,6899 h60
  text "24.60mil" at 12011.42,6899 h60
  text "4.1" at 12661.26,6899 h60
  text "9" at 9812,6779 h60
  text "InternalPlane2" at 10221.91,6779 h60
  text "Copper" at 11151.66,6779 h60
  text "1.40mil" at 12011.42,6779 h60
  text "10" at 9812,6659 h60
  text "Dielectric5" at 10221.91,6659 h60
  text "FR-4" at 11151.66,6659 h60
  text "7.87mil" at 12011.42,6659 h60
  text "4.1" at 12661.26,6659 h60
  text "11" at 9812,6539 h60
  text "MidLayer2" at 10221.91,6539 h60
  text "Copper" at 11151.66,6539 h60
  text "1.40mil" at 12011.42,6539 h60
  text "12" at 9812,6419 h60
  text "Dielectric3" at 10221.91,6419 h60
  text "FR-4" at 11151.66,6419 h60
  text "5.91mil" at 12011.42,6419 h60
  text "4.1" at 12661.26,6419 h60
  text "13" at 9812,6299 h60
  text "Bottom Layer" at 10221.91,6299 h60
  text "Copper" at 11151.66,6299 h60
  text "1.40mil" at 12011.42,6299 h60
  text "14" at 9812,6179 h60
  text "Bottom Solder" at 10221.91,6179 h60
  text "Solder Resist" at 11151.66,6179 h60
  text "0.80mil" at 12011.42,6179 h60
  text "3.3" at 12661.26,6179 h60
  text "15" at 9812,6059 h60
  text "Bottom Overlay" at 10221.91,6059 h60
  text ".Layer_Name" at 577,-858.49 h60
M13 Component Bodies Top:
  text ".Layer_Name" at 577,-858.49 h60
M14 Component Bodies Bottom:
  text ".Layer_Name" at 577,-858.49 h60
M15 Courtyards Top:
  text ".Layer_Name" at 577,-858.49 h60
M16 Courtyards Bottom:
  text ".Layer_Name" at 577,-858.49 h60
Drill Drawing:
  circle w1: c3157.97,947.55 r24.89
  circle w1: c3157.97,947.55 r14.93
  circle w1: c3157.97,1992.79 r24.89
  lines w1: 2444.65,-36.17 2457.09,-36.17 2457.09,-48.62 2481.98,-48.62 2481.98,-36.17 2494.42,-36.17 2494.42,-11.29 2481.98,-11.29 2481.98,1.16 2457.09,1.16 2457.09,-11.29 2444.65,-11.29 2444.65,-36.17 ; 2444.65,100.7 2457.09,125.59 2444.65,150.48 2469.53,138.03 2494.42,150.48 2481.98,125.59 2494.42,100.7 2469.53,113.15 2444.65,100.7 ; 2454.6,-31.2 2462.07,-31.2 2462.07,-38.66 2477,-38.66 2477,-31.2 2484.47,-31.2 2484.47,-16.26 2477,-16.26 2477,-8.8 2462.07,-8.8 2462.07,-16.26 2454.6,-16.26 2454.6,-31.2 ; 2454.6,110.66 2462.07,125.59 2454.6,140.52 2469.53,133.06 2484.47,140.52 2477,125.59 2484.47,110.66 2469.53,118.12 2454.6,110.66 ; 3133.08,636.47 3145.52,648.91 3133.08,661.35 3145.52,661.35 3157.97,673.8 3170.41,661.35 3182.85,661.35 3170.41,648.91 3182.85,636.47 3170.41,636.47 3157.97,624.02 3145.52,636.47 3133.08,636.47 ; 3133.08,823.12 3157.97,773.34 3182.85,823.12 3133.08,823.12 ; 3133.08,1071.98 3133.08,1121.76 3182.85,1121.76 3182.85,1071.98 3133.08,1071.98 ; 3133.08,1246.19 3157.97,1271.08 3182.85,1246.19 3157.97,1221.3 3133.08,1246.19 ; 3133.08,1383.07 3133.08,1407.95 3145.52,1407.95 3145.52,1420.4 3170.41,1420.4 3170.41,1407.95 3182.85,1407.95 3182.85,1383.07 3170.41,1383.07 3170.41,1370.62 3145.52,1370.62 3145.52,1383.07 3133.08,1383.07 ; 3133.08,1519.94 3145.52,1544.83 3133.08,1569.72 3157.97,1557.27 3182.85,1569.72 3170.41,1544.83 3182.85,1519.94 3157.97,1532.39 3133.08,1519.94 ; 3133.08,1681.71 3145.52,1694.15 3133.08,1706.59 3145.52,1706.59 3157.97,1719.04 3170.41,1706.59 3182.85,1706.59 3170.41,1694.15 3182.85,1681.71 3170.41,1681.71 3157.97,1669.26 3145.52,1681.71 3133.08,1681.71 ; 3133.08,1868.36 3157.97,1818.58 3182.85,1868.36 3133.08,1868.36 ; 3133.08,2117.22 3133.08,2167 3182.85,2167 3182.85,2117.22 3133.08,2117.22 ; 3133.08,2266.54 3145.52,2266.54 3157.97,2278.99 3170.41,2266.54 3182.85,2266.54 3182.85,2278.99 3170.41,2291.43 3182.85,2303.87 3182.85,2316.32 3170.41,2316.32 3157.97,2303.87 3145.52,2316.32 3133.08,2316.32 3133.08,2303.87 3145.52,2291.43 3133.08,2278.99 3133.08,2266.54 ; 3143.04,641.44 3150.5,648.91 3143.04,656.38 3150.5,656.38 3157.97,663.84 3165.43,656.38 3172.9,656.38 3165.43,648.91 3172.9,641.44 3165.43,641.44 3157.97,633.98 3150.5,641.44 3143.04,641.44 ; 3143.04,813.16 3157.97,783.3 3172.9,813.16 3143.04,813.16 ; 3143.04,1081.94 3143.04,1111.8 3172.9,1111.8 3172.9,1081.94 3143.04,1081.94
  lines w12: 3065.25,280.59 5183.27,280.59 ; 3065.25,2371.07 5183.27,2371.07 ; 3435.61,131.27 3435.61,2520.39 ; 3792.61,131.27 3792.61,2520.39 ; 4454.18,131.27 4454.18,2520.39 ; 4738.32,131.27 4738.32,2520.39 ; 3065.25,131.27 3065.25,2520.39 5183.27,2520.39 5183.27,131.27 3065.25,131.27
  text "Symbol" at 3154.84,2415.86 h72
  text "Quantity" at 3480.41,2415.86 h72
  text "Finished Hole Size" at 3837.41,2415.86 h72
  text "Plated" at 4498.97,2415.86 h72
  text "Hole Type" at 4783.11,2415.86 h72
  text "2" at 3480.41,2266.54 h60
  text "51.18mil (1.300mm)" at 3837.41,2266.54 h60
  text "NPTH" at 4498.97,2266.54 h60
  text "Round" at 4783.11,2266.54 h60
  text "12" at 3480.41,2117.22 h60
  text "7.87mil (0.200mm)" at 3837.41,2117.22 h60
  text "PTH" at 4498.97,2117.22 h60
  text "Round" at 4783.11,2117.22 h60
  text "147" at 3480.41,1967.9 h60
  text "8.00mil (0.203mm)" at 3837.41,1967.9 h60
  text "PTH" at 4498.97,1967.9 h60
  text "Round" at 4783.11,1967.9 h60
  text "54" at 3480.41,1818.58 h60
  text "8.10mil (0.206mm)" at 3837.41,1818.58 h60
  text "PTH" at 4498.97,1818.58 h60
  text "Round" at 4783.11,1818.58 h60
  text "60" at 3480.41,1669.26 h60
  text "10.00mil (0.254mm)" at 3837.41,1669.26 h60
  text "PTH" at 4498.97,1669.26 h60
  text "Round" at 4783.11,1669.26 h60
  text "1" at 3480.41,1519.94 h60
  text "39.37mil (1.000mm)" at 3837.41,1519.94 h60
  text "PTH" at 4498.97,1519.94 h60
  text "Round" at 4783.11,1519.94 h60
  text "45" at 3480.41,1370.62 h60
  text "40.00mil (1.016mm)" at 3837.41,1370.62 h60
  text "PTH" at 4498.97,1370.62 h60
  text "Round" at 4783.11,1370.62 h60
  text "2" at 3480.41,1221.3 h60
  text "51.18mil (1.300mm)" at 3837.41,1221.3 h60
  text "PTH" at 4498.97,1221.3 h60
  text "Round" at 4783.11,1221.3 h60
  text "4" at 3480.41,1071.98 h60
  text "62.99mil (1.600mm)" at 3837.41,1071.98 h60
  text "PTH" at 4498.97,1071.98 h60
  text "Round" at 4783.11,1071.98 h60
  text "2" at 3480.41,922.66 h60
  text "66.93mil (1.700mm)" at 3837.41,922.66 h60
  text "PTH" at 4498.97,922.66 h60
  text "Round" at 4783.11,922.66 h60
  text "4" at 3480.41,773.34 h60
  text "125.98mil (3.200mm)" at 3837.41,773.34 h60
  text "PTH" at 4498.97,773.34 h60
  text "Round" at 4783.11,773.34 h60
  text "2" at 3480.41,624.02 h60
  text "27.56mil (0.700mm)" at 3837.41,624.02 h60
  text "PTH" at 4498.97,624.02 h60
  text "Slot" at 4783.11,624.02 h60
  text "2" at 3480.41,474.7 h60
  text "27.56mil (0.700mm)" at 3837.41,474.7 h60
  text "PTH" at 4498.97,474.7 h60
  text "Slot" at 4783.11,474.7 h60
  text "2" at 3480.41,325.38 h60
  text "27.56mil (0.700mm)" at 3837.41,325.38 h60
  text "PTH" at 4498.97,325.38 h60
  text "Slot" at 4783.11,325.38 h60
  text "339 Total" at 3480.41,176.06 h60
  text ".Layer_Name" at 577,-858.49 h60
